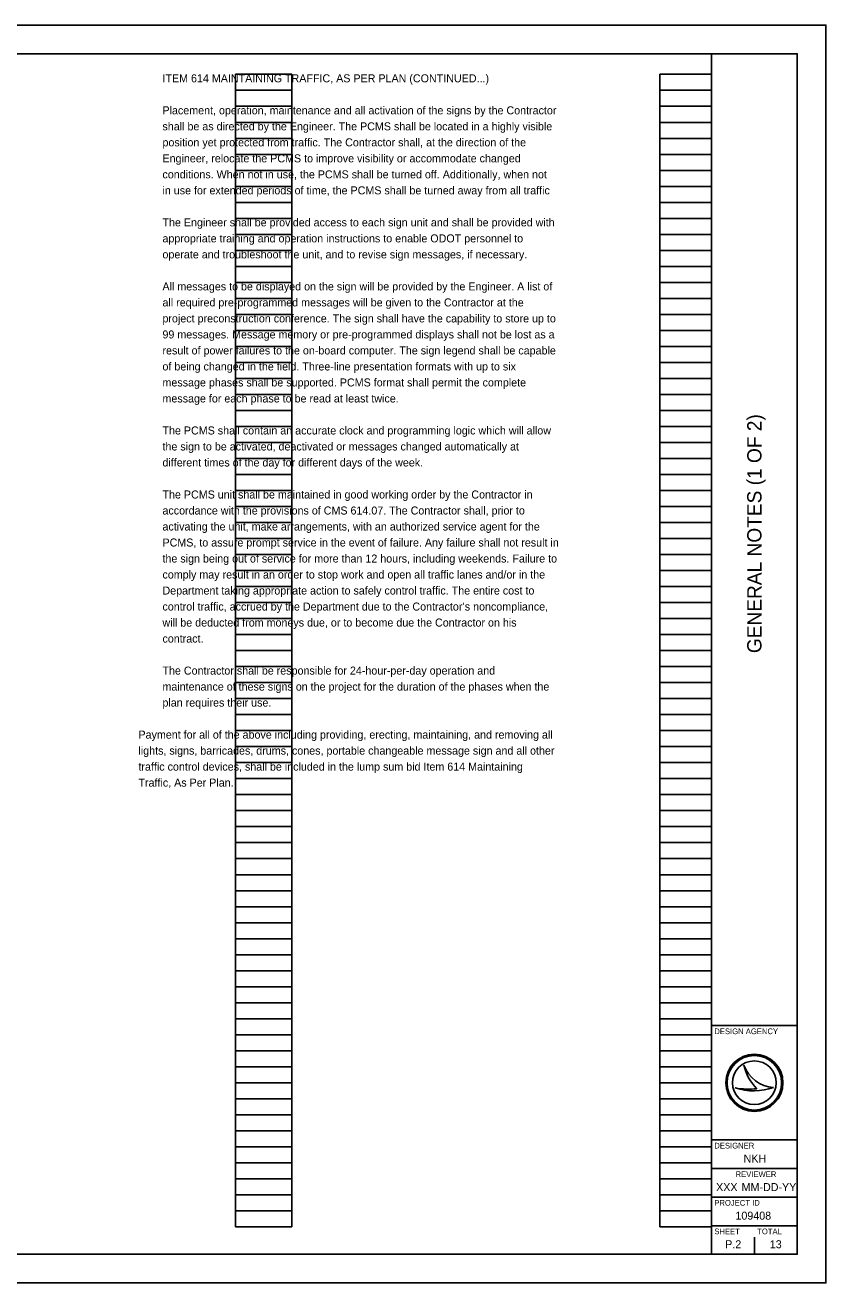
# Model space of a CAD drawing. Extents: x 0 to 34, y 0 to 22.
# Drawn here: x 20 to 34, y 0 to 22 of the extents above; entities that cross this region are included whole.
import ezdxf

# ---------------------------------------------------------------- set-up
doc = ezdxf.new("R2010")
doc.units = 0
for name, color, linetype in [('Default', 7, 'Continuous'), ('SH_Border', 7, 'Continuous'), ('SH_Cut_Line', 7, 'Continuous'), ('SH_Data', 7, 'Continuous'), ('SH_Text', 7, 'Continuous')]:
    doc.layers.add(name, color=color, linetype=linetype)

msp = doc.modelspace()

# ---------------------------------------------------------------- linework, layer by layer
at = {"layer": 'SH_Border'}
for p, q in [((32, 0.5), (32, 21.5)), ((32, 4.5), (33.5, 4.5)), ((32, 2.5), (33.5, 2.5)), ((32, 2), (33.5, 2)), ((32, 1.5), (33.5, 1.5)), ((32, 1), (33.5, 1))]:
    msp.add_line(p, q, dxfattribs=at)
msp.add_lwpolyline([(1.5, 21.5), (33.5, 21.5), (33.5, 0.5), (1.5, 0.5)], close=True, dxfattribs=at)
at = {"layer": 'SH_Cut_Line'}
msp.add_lwpolyline([(0, 0), (34, 0), (34, 22), (0, 22)], close=True, dxfattribs=at)
at = {"layer": 'SH_Data'}
for p, q in [((23.68, 0.98), (23.68, 21.14)), ((23.68, 21.14), (24.66, 21.14)), ((24.66, 0.98), (24.66, 21.14)), ((31.1, 0.98), (31.1, 21.14)), ((31.1, 21.14), (32, 21.14)), ((32, 0.98), (32, 21.14)), ((23.68, 20.86), (24.66, 20.86)), ((31.1, 20.86), (32, 20.86)), ((23.68, 20.58), (24.66, 20.58)), ((31.1, 20.58), (32, 20.58)), ((23.68, 20.3), (24.66, 20.3)), ((31.1, 20.3), (32, 20.3)), ((23.68, 20.02), (24.66, 20.02)), ((31.1, 20.02), (32, 20.02)), ((23.68, 19.74), (24.66, 19.74)), ((31.1, 19.74), (32, 19.74)), ((23.68, 19.46), (24.66, 19.46)), ((31.1, 19.46), (32, 19.46)), ((23.68, 19.18), (24.66, 19.18)), ((31.1, 19.18), (32, 19.18)), ((23.68, 18.9), (24.66, 18.9)), ((31.1, 18.9), (32, 18.9)), ((23.68, 18.62), (24.66, 18.62)), ((31.1, 18.62), (32, 18.62)), ((23.68, 18.34), (24.66, 18.34)), ((31.1, 18.34), (32, 18.34)), ((23.68, 18.06), (24.66, 18.06)), ((31.1, 18.06), (32, 18.06)), ((23.68, 17.78), (24.66, 17.78)), ((31.1, 17.78), (32, 17.78)), ((23.68, 17.5), (24.66, 17.5)), ((31.1, 17.5), (32, 17.5)), ((23.68, 17.22), (24.66, 17.22)), ((31.1, 17.22), (32, 17.22)), ((23.68, 16.94), (24.66, 16.94)), ((31.1, 16.94), (32, 16.94)), ((23.68, 16.66), (24.66, 16.66)), ((31.1, 16.66), (32, 16.66)), ((23.68, 16.38), (24.66, 16.38)), ((31.1, 16.38), (32, 16.38)), ((23.68, 16.1), (24.66, 16.1)), ((31.1, 16.1), (32, 16.1)), ((23.68, 15.82), (24.66, 15.82)), ((31.1, 15.82), (32, 15.82)), ((23.68, 15.54), (24.66, 15.54)), ((31.1, 15.54), (32, 15.54)), ((23.68, 15.26), (24.66, 15.26)), ((31.1, 15.26), (32, 15.26)), ((23.68, 14.98), (24.66, 14.98)), ((31.1, 14.98), (32, 14.98)), ((23.68, 14.7), (24.66, 14.7)), ((31.1, 14.7), (32, 14.7)), ((23.68, 14.42), (24.66, 14.42)), ((31.1, 14.42), (32, 14.42)), ((23.68, 14.14), (24.66, 14.14)), ((31.1, 14.14), (32, 14.14)), ((23.68, 13.86), (24.66, 13.86)), ((31.1, 13.86), (32, 13.86)), ((23.68, 13.58), (24.66, 13.58)), ((31.1, 13.58), (32, 13.58)), ((23.68, 13.3), (24.66, 13.3)), ((31.1, 13.3), (32, 13.3)), ((23.68, 13.02), (24.66, 13.02)), ((31.1, 13.02), (32, 13.02)), ((23.68, 12.74), (24.66, 12.74)), ((31.1, 12.74), (32, 12.74)), ((23.68, 12.46), (24.66, 12.46)), ((31.1, 12.46), (32, 12.46)), ((23.68, 12.18), (24.66, 12.18)), ((31.1, 12.18), (32, 12.18)), ((23.68, 11.9), (24.66, 11.9)), ((31.1, 11.9), (32, 11.9)), ((23.68, 11.62), (24.66, 11.62)), ((31.1, 11.62), (32, 11.62)), ((23.68, 11.34), (24.66, 11.34)), ((31.1, 11.34), (32, 11.34)), ((23.68, 11.06), (24.66, 11.06)), ((31.1, 11.06), (32, 11.06)), ((23.68, 10.78), (24.66, 10.78)), ((31.1, 10.78), (32, 10.78)), ((23.68, 10.5), (24.66, 10.5)), ((31.1, 10.5), (32, 10.5)), ((23.68, 10.22), (24.66, 10.22)), ((31.1, 10.22), (32, 10.22)), ((23.68, 9.94), (24.66, 9.94)), ((31.1, 9.94), (32, 9.94)), ((23.68, 9.66), (24.66, 9.66)), ((31.1, 9.66), (32, 9.66)), ((23.68, 9.38), (24.66, 9.38)), ((31.1, 9.38), (32, 9.38)), ((23.68, 9.1), (24.66, 9.1)), ((31.1, 9.1), (32, 9.1)), ((23.68, 8.82), (24.66, 8.82)), ((31.1, 8.82), (32, 8.82)), ((23.68, 8.54), (24.66, 8.54)), ((31.1, 8.54), (32, 8.54)), ((23.68, 8.26), (24.66, 8.26)), ((31.1, 8.26), (32, 8.26)), ((23.68, 7.98), (24.66, 7.98)), ((31.1, 7.98), (32, 7.98)), ((23.68, 7.7), (24.66, 7.7)), ((31.1, 7.7), (32, 7.7)), ((23.68, 7.42), (24.66, 7.42)), ((31.1, 7.42), (32, 7.42)), ((23.68, 7.14), (24.66, 7.14)), ((31.1, 7.14), (32, 7.14)), ((23.68, 6.86), (24.66, 6.86)), ((31.1, 6.86), (32, 6.86)), ((23.68, 6.58), (24.66, 6.58)), ((31.1, 6.58), (32, 6.58)), ((23.68, 6.3), (24.66, 6.3)), ((31.1, 6.3), (32, 6.3)), ((23.68, 6.02), (24.66, 6.02)), ((31.1, 6.02), (32, 6.02)), ((23.68, 5.74), (24.66, 5.74)), ((31.1, 5.74), (32, 5.74)), ((23.68, 5.46), (24.66, 5.46)), ((31.1, 5.46), (32, 5.46)), ((23.68, 5.18), (24.66, 5.18)), ((31.1, 5.18), (32, 5.18)), ((23.68, 4.9), (24.66, 4.9)), ((31.1, 4.9), (32, 4.9)), ((23.68, 4.62), (24.66, 4.62)), ((31.1, 4.62), (32, 4.62)), ((23.68, 4.34), (24.66, 4.34)), ((31.1, 4.34), (32, 4.34)), ((23.68, 4.06), (24.66, 4.06)), ((31.1, 4.06), (32, 4.06)), ((23.68, 3.78), (24.66, 3.78)), ((31.1, 3.78), (32, 3.78)), ((32.567, 3.81), (32.567, 3.81)), ((23.68, 3.5), (24.66, 3.5)), ((31.1, 3.5), (32, 3.5)), ((32.417, 3.41), (32.417, 3.41)), ((32.75, 3.5), (32.75, 3.5)), ((33.087, 3.419), (33.087, 3.419)), ((23.68, 3.22), (24.66, 3.22)), ((31.1, 3.22), (32, 3.22)), ((23.68, 2.94), (24.66, 2.94)), ((31.1, 2.94), (32, 2.94)), ((23.68, 2.66), (24.66, 2.66)), ((31.1, 2.66), (32, 2.66)), ((23.68, 2.38), (24.66, 2.38)), ((31.1, 2.38), (32, 2.38)), ((23.68, 2.1), (24.66, 2.1)), ((31.1, 2.1), (32, 2.1)), ((23.68, 1.82), (24.66, 1.82)), ((31.1, 1.82), (32, 1.82)), ((23.68, 1.54), (24.66, 1.54)), ((31.1, 1.54), (32, 1.54)), ((23.68, 1.26), (24.66, 1.26)), ((31.1, 1.26), (32, 1.26)), ((23.68, 0.98), (24.66, 0.98)), ((31.1, 0.98), (32, 0.98)), ((32.375, 0.675), (32.375, 0.675)), ((32.75, 0.5), (32.75, 0.8))]:
    msp.add_line(p, q, dxfattribs=at)
for radius in [0.5, 0.477, 0.477, 0.382]:
    msp.add_circle((32.75, 3.5), radius, dxfattribs=at)
for centre, radius, start, end in [((33.116, 3.998), 0.58, 198.9257, 198.9319), ((33.347, 3.97), 0.796, 191.6379, 191.6421), ((33.116, 3.998), 0.58, 198.9319, 267.1657), ((33.347, 3.97), 0.796, 191.6421, 226.0947), ((32.739, 4.37), 1.013, 251.4576, 290.0832), ((32.648, 4.654), 1.266, 259.4964, 259.4995), ((32.739, 4.37), 1.013, 251.4527, 251.4576), ((32.648, 4.654), 1.266, 259.4995, 276.6672)]:
    msp.add_arc(centre, radius, start, end, dxfattribs=at)

# ---------------------------------------------------------------- texts
at = {"layer": 'Default'}
msp.add_text('ITEM 614 MAINTAINING TRAFFIC, AS PER PLAN (CONTINUED...)', height=0.14, dxfattribs=at).set_placement((22.4, 21))
at = {"layer": 'SH_Data'}
msp.add_text('GENERAL NOTES (1 OF 2)', height=0.25, rotation=90, dxfattribs=at).set_placement((32.875, 11.015))
for s, height, p in [('DESIGN AGENCY', 0.1, (32.05, 4.35)), ('DESIGNER', 0.1, (32.05, 2.35)), ('NKH', 0.14, (32.562, 2.105)), ('REVIEWER', 0.1, (32.422, 1.85)), ('XXX', 0.14, (32.081, 1.605)), ('MM-DD-YY', 0.14, (32.527, 1.605)), ('PROJECT ID', 0.1, (32.05, 1.35)), ('109408', 0.14, (32.419, 1.105)), ('SHEET', 0.1, (32.05, 0.85)), ('TOTAL', 0.1, (32.8, 0.85)), ('P.2', 0.14, (32.24, 0.605)), ('13', 0.14, (33.02, 0.605))]:
    msp.add_text(s, height=height, dxfattribs=at).set_placement(p)
at = {"layer": 'SH_Text'}
for s, p in [('Placement, operation, maintenance and all activation of the signs by the Contractor', (22.4, 20.44)), ('shall be as directed by the Engineer. The PCMS shall be located in a highly visible', (22.4, 20.16)), ('position yet protected from traffic. The Contractor shall, at the direction of the ', (22.4, 19.88)), ('Engineer, relocate the PCMS to improve visibility or accommodate changed ', (22.4, 19.6)), ('conditions. When not in use, the PCMS shall be turned off. Additionally, when not ', (22.4, 19.32)), ('in use for extended periods of time, the PCMS shall be turned away from all traffic', (22.4, 19.04)), ('The Engineer shall be provided access to each sign unit and shall be provided with', (22.4, 18.48)), ('appropriate training and operation instructions to enable ODOT personnel to ', (22.4, 18.2)), ('operate and troubleshoot the unit, and to revise sign messages, if necessary.', (22.4, 17.92)), ('All messages to be displayed on the sign will be provided by the Engineer. A list of ', (22.4, 17.36)), ('all required pre-programmed messages will be given to the Contractor at the ', (22.4, 17.08)), ('project preconstruction conference. The sign shall have the capability to store up to ', (22.4, 16.8)), ('99 messages. Message memory or pre-programmed displays shall not be lost as a ', (22.4, 16.52)), ('result of power failures to the on-board computer. The sign legend shall be capable ', (22.4, 16.24)), ('of being changed in the field. Three-line presentation formats with up to six ', (22.4, 15.96)), ('message phases shall be supported. PCMS format shall permit the complete ', (22.4, 15.68)), ('message for each phase to be read at least twice.', (22.4, 15.4)), ('The PCMS shall contain an accurate clock and programming logic which will allow ', (22.4, 14.84)), ('the sign to be activated, deactivated or messages changed automatically at ', (22.4, 14.56)), ('different times of the day for different days of the week.', (22.4, 14.28)), ('The PCMS unit shall be maintained in good working order by the Contractor in ', (22.4, 13.72)), ('accordance with the provisions of CMS 614.07. The Contractor shall, prior to ', (22.4, 13.44)), ('activating the unit, make arrangements, with an authorized service agent for the ', (22.4, 13.16)), ('PCMS, to assure prompt service in the event of failure. Any failure shall not result in ', (22.4, 12.88)), ('the sign being out of service for more than 12 hours, including weekends. Failure to ', (22.4, 12.6)), ('comply may result in an order to stop work and open all traffic lanes and/or in the ', (22.4, 12.32)), ('Department taking appropriate action to safely control traffic. The entire cost to ', (22.4, 12.04)), ('control traffic, accrued by the Department due to the Contractor’s noncompliance, ', (22.4, 11.76)), ('will be deducted from moneys due, or to become due the Contractor on his ', (22.4, 11.48)), ('contract.', (22.4, 11.2)), ('The Contractor shall be responsible for 24-hour-per-day operation and ', (22.4, 10.64)), ('maintenance of these signs on the project for the duration of the phases when the ', (22.4, 10.36)), ('plan requires their use.', (22.4, 10.08)), ('Payment for all of the above including providing, erecting, maintaining, and removing all ', (21.98, 9.52)), ('lights, signs, barricades, drums, cones, portable changeable message sign and all other ', (21.98, 9.24)), ('traffic control devices, shall be included in the lump sum bid Item 614 Maintaining ', (21.98, 8.96)), ('Traffic, As Per Plan.', (21.98, 8.68))]:
    msp.add_text(s, height=0.14, dxfattribs=at).set_placement(p)

doc.saveas('drawing.dxf')
